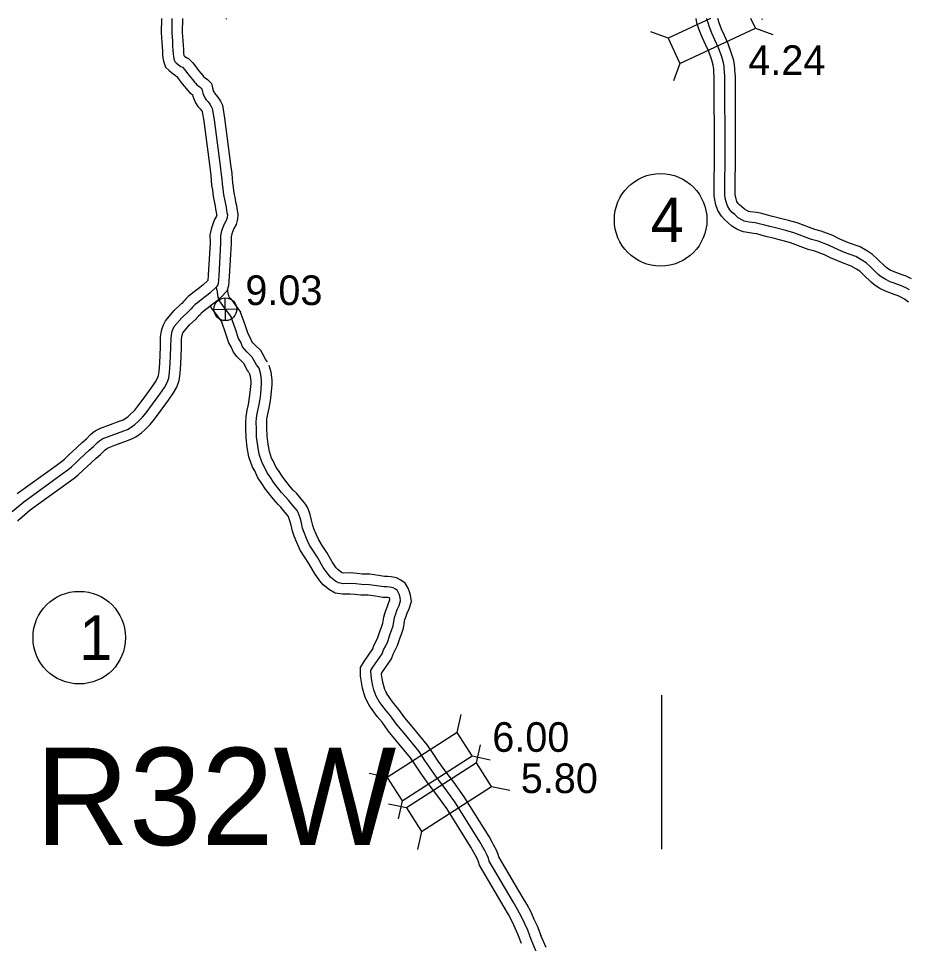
# Model space of a CAD drawing. Extents: x 31699 to 244310, y -8841 to 11474.
# Drawn here: x 100628 to 101474, y 4763 to 5642 of the extents above; entities that cross this region are included whole.
import ezdxf

# ---------------------------------------------------------------- set-up
doc = ezdxf.new("R2010")
doc.units = 0
for name, color, linetype in [('B_Logo', 7, 'Continuous'), ('Default', 7, 'Continuous'), ('Level 21', 7, 'Continuous'), ('R_Border', 7, 'Continuous'), ('R_Border Notes', 7, 'Continuous'), ('R_XS_EARTHWORK_STAGE1', 7, 'Continuous'), ('R_XS_EARTHWORK_STAGE2', 7, 'Continuous'), ('S_WALL', 7, 'Continuous'), ('S_WALL_ANNOT', 7, 'Continuous')]:
    doc.layers.add(name, color=color, linetype=linetype)

msp = doc.modelspace()

# ---------------------------------------------------------------- linework, layer by layer
at = {"layer": 'B_Logo'}
for points in [[(100773.57, 5642.27), (100773.39, 5628.8), (100773.94, 5620.58), (100774.24, 5615.9), (100774.55, 5612.15), (100774.66, 5608.54), (100774.91, 5606.07), (100775.23, 5604.06), (100775.56, 5603.06), (100776.08, 5601.72), (100777.67, 5600.24), (100779.53, 5598.55), (100782.05, 5596.6), (100783.51, 5595.92), (100785.9, 5593.5), (100787.55, 5591.22), (100791.12, 5586.59), (100793.37, 5583.9), (100794.95, 5581.88), (100795.88, 5580.67), (100797.2, 5579.26), (100799.19, 5577.85), (100800.59, 5576.7), (100802.04, 5575.29), (100802.37, 5573.95), (100803.02, 5571.21), (100803.61, 5569.6), (100804.79, 5566.98), (100806.11, 5564.97), (100807.96, 5563.02), (100809.62, 5560.81), (100811, 5558.66), (100811.92, 5556.78), (100813.72, 5546.08), (100819.44, 5502.26), (100820.45, 5493.97), (100820.88, 5489.16), (100821.26, 5484.74), (100821.9, 5480.73), (100822.27, 5477.12), (100822.91, 5473.17), (100823.43, 5470.49), (100824.33, 5465.94), (100824.98, 5462.86), (100825.36, 5459.92), (100825.81, 5457.98), (100826.27, 5455.64), (100826.05, 5453.3), (100825.23, 5450.43), (100823.28, 5446.97), (100820.83, 5440.43), (100819.74, 5435.69), (100819.83, 5428.88), (100818.02, 5397.81), (100817.57, 5390.19), (100816.9, 5388.39), (100815.48, 5386.8)], [(101283.24, 5638.27), (101282.46, 5640.68), (101282.16, 5642.27)], [(101474.81, 5384.33), (101471.87, 5386.06), (101467.88, 5388.02), (101463.56, 5389.52), (101459.37, 5391.08), (101456.31, 5392.1), (101451.52, 5394.41), (101448, 5396.7), (101445.09, 5399.12), (101437.67, 5406.32), (101433.62, 5409.96), (101429.57, 5412.65), (101423.66, 5416.1), (101413.15, 5419.91), (101403.85, 5423.91), (101397.87, 5426.75), (101387.82, 5430.63), (101381.64, 5432.27), (101364.94, 5438.59), (101357.29, 5440.77), (101347.37, 5443.24), (101342.05, 5444.48), (101337.19, 5445.78), (101332, 5447.21), (101328.07, 5447.97), (101322.21, 5448.74), (101319.41, 5449.23), (101317.75, 5449.78), (101315.29, 5450.86), (101311.97, 5452.95), (101308.66, 5455.85), (101306.27, 5458), (101304.02, 5460.42), (101301.71, 5464.11), (101300.34, 5468.06), (101299.56, 5471.48), (101299.18, 5474.82), (101299.14, 5478.16), (101299.51, 5514.79), (101299.24, 5586.64), (101298.75, 5592.65), (101298.69, 5594.53), (101298.44, 5597.07), (101298, 5600.21), (101296.23, 5605.84), (101293.16, 5614.48), (101289.87, 5621.85), (101286.85, 5628.35), (101284.29, 5634.85), (101283.24, 5638.27)], [(100815.48, 5386.8), (100809.98, 5381.62), (100806.37, 5378.7), (100804.22, 5377.04), (100801.94, 5375.32), (100799.73, 5373.66), (100797.79, 5372.07), (100795.71, 5370.48), (100794.17, 5368.95), (100793.23, 5367.89), (100791.75, 5366.36), (100789.94, 5364.5), (100789.27, 5363.83), (100782.91, 5357.88)], [(100815.48, 5386.8), (100815.87, 5385.06), (100816.14, 5384.45), (100816.33, 5383.72), (100816.46, 5382.51), (100816.58, 5381.58), (100816.77, 5380.04), (100817.29, 5377.63), (100817.81, 5375.62), (100818.54, 5374.08), (100819.92, 5371.6), (100821.77, 5369.51), (100829.74, 5358.57)], [(100621.68, 5173.63), (100632.6, 5183.09), (100669.18, 5209.44), (100674.59, 5213.33), (100677.95, 5216.12), (100682.74, 5220.61), (100685.83, 5223.46), (100694.9, 5232.02), (100698.91, 5235.42), (100702.92, 5239.29), (100704.89, 5241.19), (100705.81, 5241.87), (100707.93, 5242.98), (100710.84, 5244.22), (100715.94, 5246.1), (100727.74, 5250.49), (100731.18, 5251.81), (100733.96, 5253.26), (100738.31, 5256.33), (100741.14, 5258.91), (100743.96, 5261.69), (100745.67, 5263.32), (100749.2, 5267.66), (100755.21, 5275.9), (100762, 5285.23), (100766.5, 5291.71), (100768.97, 5296.23), (100770.63, 5300.6), (100771.29, 5305.83), (100771.9, 5314.26), (100772.54, 5329.78), (100772.8, 5338.88), (100773.53, 5343.43), (100773.91, 5344.98), (100774.67, 5347.33), (100775.78, 5349.42), (100782.91, 5357.88)], [(100856.37, 5309.96), (100853.99, 5313.2), (100849.95, 5320.56), (100845.16, 5325.11), (100842.92, 5327.55), (100840.75, 5330.32), (100838.95, 5334.64), (100836.77, 5338.29), (100833.98, 5346.87), (100829.74, 5358.57)], [(101115.24, 4766.95), (101111.77, 4775.92), (101108.95, 4782.03), (101106.06, 4788.54), (101102.22, 4795.64), (101097.99, 4802.73), (101075.23, 4841.57), (101074.39, 4844.3), (101073, 4847.62), (101070.61, 4852.2), (101069.24, 4854.59), (101066.43, 4859.7), (101043.23, 4896.93), (101033.43, 4910.55), (101025.15, 4921.26), (101018.55, 4930.66), (101014.12, 4937.21), (101008.46, 4945.62), (100994.22, 4962.93), (100987.03, 4971.58), (100981.25, 4979.52), (100976.63, 4985.2), (100973.51, 4989.3), (100970.65, 4993.33), (100969.42, 4995.39), (100969.01, 4996.05), (100967.84, 4998.31), (100966.67, 5000.9), (100965.63, 5004.16), (100964.63, 5008.15), (100963.56, 5013.29), (100962.89, 5017.96), (100962.82, 5022.77), (100964.7, 5025.94), (100973.31, 5038.44), (100974.79, 5042.2), (100976.8, 5046.24), (100978.74, 5050.22), (100981.1, 5057.34), (100982.31, 5060.57), (100983.85, 5065.14), (100984.76, 5071.17), (100985.51, 5073.99), (100986.34, 5076.47), (100987.49, 5079.63), (100988.26, 5081.85), (100989.49, 5084.27), (100991.02, 5088.98), (100990.57, 5092.11), (100989.73, 5095.04), (100989.11, 5096.5), (100987.74, 5098.89), (100986.13, 5100.07), (100983.91, 5101.17), (100980.64, 5101.79), (100977.9, 5102.02), (100974.9, 5102.11), (100968.49, 5103.09), (100960.95, 5104.11), (100953.75, 5104.27), (100948.55, 5104.93), (100943.21, 5105.32), (100936.35, 5105.08), (100932.01, 5105.82), (100928.99, 5107.51), (100924.4, 5111.32), (100921.96, 5114.16), (100917.47, 5120.45), (100912.21, 5129.6), (100908.11, 5136.16), (100904.36, 5141.85), (100901.47, 5148.23), (100899.19, 5153.81), (100897.8, 5157.87), (100896.65, 5163.13), (100895.32, 5167.86), (100893.64, 5172.92), (100892.48, 5174.77), (100888.62, 5179.33), (100884.54, 5184.48), (100881.71, 5187.25), (100877.71, 5191.73), (100870.71, 5200.66), (100866.62, 5207.01), (100864.04, 5210.65), (100861.08, 5217.03), (100859.23, 5220.08), (100856.52, 5228.19), (100855.07, 5236.13), (100854.01, 5244.6), (100853.82, 5252.56), (100853.67, 5258.24), (100853.94, 5262.72), (100854.99, 5268.15), (100856.04, 5273.72), (100857.34, 5280.49), (100857.93, 5285.71), (100858.86, 5294.95), (100858.81, 5298.23), (100857.99, 5304.03), (100856.37, 5309.96)], [(101120, 4755.72), (101115.24, 4766.95)]]:
    msp.add_lwpolyline(points, dxfattribs=at)
at = {"layer": 'Default'}
msp.add_line((101239.15, 4999.1), (101239.15, 4852.8), dxfattribs=at)
at = {"layer": 'Level 21'}
for p, q in [((100824.64, 5355.15), (100824.14, 5376.85)), ((100813.54, 5365.75), (100835.24, 5366.25))]:
    msp.add_line(p, q, dxfattribs=at)
msp.add_circle((100824.39, 5366), 10.85, dxfattribs=at)
at = {"layer": 'R_Border Notes'}
for centre in [(101238.18, 5450.95), (100685.48, 5053.87)]:
    msp.add_circle(centre, 44, dxfattribs=at)
at = {"layer": 'R_XS_EARTHWORK_STAGE1'}
for p, q in [((100824.76, 5642.27), (100825.4, 5641.59)), ((101334.42, 5642.27), (101334.73, 5641.25)), ((101245.41, 5623.54), (101228.88, 5629.58)), ((101328.35, 5633.01), (101344.89, 5626.97)), ((101256.54, 5599.61), (101250.51, 5583.07)), ((101044.78, 4963.74), (101048.54, 4980.93)), ((101063.22, 4934.74), (101066.98, 4951.94)), ((101059.03, 4941.52), (101076.23, 4937.76)), ((100978.11, 4920.99), (100960.92, 4924.75)), ((101077.47, 4912.52), (101094.67, 4908.76)), ((100992.36, 4898.77), (100988.6, 4881.57)), ((100996.55, 4891.99), (100979.36, 4895.75)), ((101010.8, 4869.77), (101007.04, 4852.58))]:
    msp.add_line(p, q, dxfattribs=at)
msp.add_lwpolyline([(101285.66, 5642.27), (101245.41, 5623.54), (101256.54, 5599.61), (101328.35, 5633.01), (101324.05, 5642.27)], dxfattribs=at)
for points in [[(100992.36, 4898.77), (101059.03, 4941.52), (101044.78, 4963.74), (100978.11, 4920.99)], [(101010.8, 4869.77), (101077.47, 4912.52), (101063.22, 4934.74), (100996.55, 4891.99)]]:
    msp.add_lwpolyline(points, close=True, dxfattribs=at)
at = {"layer": 'R_XS_EARTHWORK_STAGE2'}
for points in [[(100763.56, 5642.27), (100763.39, 5628.53), (100763.96, 5619.92), (100764.27, 5615.16), (100764.56, 5611.59), (100764.68, 5607.89), (100764.99, 5604.78), (100765.48, 5601.71), (100766.14, 5599.68), (100767.6, 5595.95), (100770.91, 5592.87), (100773.1, 5590.89), (100776.82, 5588), (100777.66, 5587.61), (100778.24, 5587.03), (100779.53, 5585.24), (100783.32, 5580.32), (100785.6, 5577.59), (100787.06, 5575.75), (100788.24, 5574.2), (100790.59, 5571.69), (100793.04, 5569.95), (100793.42, 5568.32), (100794.35, 5565.81), (100796, 5562.15), (100798.24, 5558.73), (100800.31, 5556.56), (100801.4, 5555.1), (100802.28, 5553.73), (100802.3, 5553.69), (100803.83, 5544.6), (100809.51, 5501.01), (100810.5, 5492.91), (100810.92, 5488.29), (100811.32, 5483.53), (100811.98, 5479.42), (100812.36, 5475.8), (100813.07, 5471.42), (100813.62, 5468.57), (100814.54, 5463.94), (100815.11, 5461.19), (100815.51, 5458.14), (100816.03, 5455.89), (100816.18, 5455.14), (100815.94, 5454.32), (100814.18, 5451.2), (100811.24, 5443.32), (100809.72, 5436.77), (100809.82, 5429.1), (100808.04, 5398.39), (100807.74, 5393.35)], [(100783.57, 5642.27), (100783.4, 5629.07), (100783.92, 5621.23), (100784.22, 5616.63), (100784.54, 5612.72), (100784.65, 5609.2), (100784.83, 5607.36), (100784.85, 5607.23), (100785.96, 5606.22), (100787.28, 5605.2), (100789.36, 5604.23), (100793.55, 5599.98), (100795.56, 5597.2), (100798.92, 5592.85), (100801.13, 5590.2), (100802.85, 5588.02), (100803.52, 5587.15), (100803.81, 5586.83), (100805.28, 5585.79), (100807.25, 5584.17), (100811.08, 5580.46), (100812.09, 5576.28), (100812.61, 5574.09), (100812.87, 5573.39), (100813.58, 5571.82), (100813.98, 5571.21), (100815.62, 5569.48), (100817.84, 5566.51), (100819.72, 5563.59), (100821.54, 5559.88), (100823.61, 5547.55), (100829.36, 5503.52), (100830.39, 5495.03), (100830.85, 5490.02), (100831.19, 5485.95), (100831.81, 5482.04), (100832.19, 5478.44), (100832.76, 5474.92), (100833.24, 5472.41), (100834.13, 5467.94), (100834.85, 5464.54), (100835.21, 5461.71), (100835.6, 5460.07), (100836.35, 5456.14), (100835.92, 5451.45), (100834.52, 5446.55), (100832.37, 5442.73), (100830.43, 5437.54), (100829.75, 5434.62), (100829.83, 5428.65), (100828.01, 5397.22), (100827.47, 5388.09), (100825.6, 5383.15), (100822.98, 5380.17)], [(101274.84, 5631.55), (101273.71, 5635.26), (101272.75, 5638.2), (101271.99, 5642.27)], [(101296.04, 5632.29), (101293.74, 5638.15), (101292.78, 5641.27), (101292.46, 5642.27)], [(101473.85, 5372.55), (101470.01, 5375.55), (101467.11, 5377.25), (101464.02, 5378.78), (101460.17, 5380.11), (101456.03, 5381.65), (101452.54, 5382.82), (101446.6, 5385.68), (101442.06, 5388.64), (101438.4, 5391.68), (101430.84, 5399.01), (101427.48, 5402.04), (101424.28, 5404.17), (101419.41, 5407.01), (101409.47, 5410.61), (101399.72, 5414.8), (101393.91, 5417.56), (101384.73, 5421.1), (101378.57, 5422.73), (101361.79, 5429.09), (101354.71, 5431.11), (101345.04, 5433.52), (101339.63, 5434.77), (101334.57, 5436.13), (101329.71, 5437.47), (101326.47, 5438.1), (101320.7, 5438.86), (101316.99, 5439.5), (101314.17, 5440.43), (101310.58, 5442.01), (101305.98, 5444.91), (101302.02, 5448.37), (101299.25, 5450.87), (101296.05, 5454.31), (101292.64, 5459.76), (101290.71, 5465.3), (101289.68, 5469.8), (101289.19, 5474.19), (101289.14, 5478.15), (101289.51, 5514.82), (101289.24, 5586.21), (101288.76, 5592.1), (101288.71, 5593.89), (101288.51, 5595.87), (101288.21, 5598), (101286.75, 5602.66), (101283.86, 5610.76), (101280.77, 5617.71), (101277.65, 5624.41), (101274.84, 5631.55)], [(101476.62, 5394.87), (101471.74, 5397.27), (101466.94, 5398.93), (101462.7, 5400.51), (101460.07, 5401.39), (101456.44, 5403.14), (101453.95, 5404.76), (101451.77, 5406.57), (101444.49, 5413.63), (101439.77, 5417.88), (101434.87, 5421.14), (101427.92, 5425.19), (101416.84, 5429.21), (101407.97, 5433.02), (101401.82, 5435.95), (101390.92, 5440.15), (101384.7, 5441.8), (101368.09, 5448.09), (101359.87, 5450.44), (101349.71, 5452.96), (101344.47, 5454.18), (101339.82, 5455.43), (101334.29, 5456.96), (101329.68, 5457.85), (101323.72, 5458.63), (101321.84, 5458.96), (101321.33, 5459.12), (101320, 5459.71), (101317.96, 5461), (101315.3, 5463.33), (101313.3, 5465.13), (101311.99, 5466.53), (101310.79, 5468.46), (101309.96, 5470.82), (101309.43, 5473.15), (101309.17, 5475.45), (101309.14, 5478.18), (101309.51, 5514.75), (101309.24, 5587.06), (101308.73, 5593.21), (101308.68, 5595.16), (101308.37, 5598.26), (101307.78, 5602.42), (101305.72, 5609.01), (101302.45, 5618.2), (101298.97, 5625.99), (101296.04, 5632.29)], [(100807.82, 5393.31), (100803.41, 5389.16), (100800.17, 5386.55), (100798.15, 5384.99), (100795.93, 5383.31), (100793.56, 5381.53), (100791.58, 5379.91), (100789.13, 5378.03), (100786.9, 5375.82), (100785.88, 5374.68), (100784.58, 5373.32), (100782.84, 5371.54), (100782.33, 5371.04), (100775.66, 5364.79)], [(100822.91, 5380.05), (100816.56, 5374.07), (100812.56, 5370.85), (100810.3, 5369.1), (100807.96, 5367.33), (100805.9, 5365.79), (100804, 5364.23), (100802.3, 5362.93), (100801.44, 5362.08), (100800.57, 5361.1), (100798.93, 5359.4), (100797.04, 5357.46), (100796.21, 5356.63), (100790.19, 5350.99)], [(100826.28, 5384.75), (100826.39, 5383.71), (100826.5, 5382.86), (100826.64, 5381.71), (100827.02, 5379.93), (100827.26, 5379.03), (100827.44, 5378.64), (100828.12, 5377.43), (100829.57, 5375.8), (100838.69, 5363.26)], [(100626.39, 5190.94), (100663.34, 5217.55), (100668.46, 5221.24), (100671.33, 5223.63), (100675.94, 5227.93), (100679.01, 5230.77), (100688.23, 5239.47), (100692.2, 5242.84), (100695.97, 5246.49), (100698.42, 5248.84), (100700.5, 5250.38), (100703.65, 5252.02), (100707.14, 5253.52), (100712.47, 5255.48), (100724.2, 5259.84), (100727.07, 5260.94), (100728.74, 5261.81), (100732.03, 5264.14), (100734.25, 5266.17), (100737, 5268.87), (100738.32, 5270.13), (100741.28, 5273.77), (100747.13, 5281.79), (100753.85, 5291.02), (100757.98, 5296.98), (100759.87, 5300.43), (100760.86, 5303.04), (100761.34, 5306.81), (100761.91, 5314.82), (100762.54, 5330.13), (100762.82, 5339.82), (100763.72, 5345.42), (100764.28, 5347.71), (100765.43, 5351.24), (100767.43, 5355.04), (100775.59, 5364.7)], [(100810.05, 5368.77), (100811.72, 5365.77), (100813.98, 5363.23), (100820.88, 5353.75)], [(100864.43, 5315.88), (100862.44, 5318.59), (100857.97, 5326.75), (100852.29, 5332.12), (100850.56, 5334.01), (100849.46, 5335.42), (100847.91, 5339.16), (100845.93, 5342.46), (100843.43, 5350.12), (100838.72, 5363.13)], [(100847.1, 5305.69), (100845.54, 5307.81), (100841.94, 5314.38), (100838.02, 5318.09), (100835.29, 5321.08), (100832.04, 5325.23), (100830, 5330.13), (100827.61, 5334.12), (100824.52, 5343.62), (100820.85, 5353.76)], [(100627.01, 5164.42), (100627.95, 5165.73), (100628.56, 5166.36), (100638.81, 5175.24), (100675.03, 5201.32), (100680.72, 5205.42), (100684.56, 5208.62), (100689.55, 5213.28), (100692.66, 5216.15), (100701.57, 5224.56), (100705.63, 5228), (100709.87, 5232.1), (100711.25, 5233.43), (100712.21, 5233.93), (100714.54, 5234.93), (100719.42, 5236.72), (100731.27, 5241.13), (100735.3, 5242.68), (100739.18, 5244.7), (100744.59, 5248.52), (100748.02, 5251.66), (100750.92, 5254.52), (100753.02, 5256.52), (100757.12, 5261.55), (100763.29, 5270.01), (100770.15, 5279.43), (100775.02, 5286.45), (100778.07, 5292.03), (100780.41, 5298.16), (100781.25, 5304.84), (100781.88, 5313.69), (100782.53, 5329.43), (100782.78, 5337.93), (100783.34, 5341.45), (100783.54, 5342.24), (100783.92, 5343.42), (100784.12, 5343.8), (100790.18, 5350.99)], [(101124.57, 4770.55), (101120.99, 4779.82), (101118.06, 4786.16), (101115.04, 4792.96), (101110.92, 4800.58), (101106.59, 4807.82), (101084.44, 4845.63), (101083.8, 4847.7), (101082.07, 4851.87), (101079.38, 4857.01), (101077.96, 4859.48), (101075.06, 4864.75), (101051.54, 4902.5), (101041.45, 4916.53), (101033.2, 4927.2), (101026.78, 4936.33), (101022.41, 4942.8), (101016.49, 4951.6), (101001.92, 4969.3), (100994.92, 4977.72), (100989.18, 4985.62), (100984.49, 4991.38), (100981.57, 4995.22), (100979.03, 4998.8), (100977.96, 5000.58), (100977.72, 5000.98), (100976.85, 5002.66), (100976.02, 5004.5), (100975.25, 5006.89), (100974.38, 5010.38), (100973.41, 5015.02), (100972.88, 5018.74), (100972.86, 5020.09), (100973.13, 5020.54), (100982.2, 5033.71), (100983.94, 5038.15), (100985.77, 5041.83), (100988.02, 5046.43), (100990.52, 5054), (100991.74, 5057.21), (100993.6, 5062.78), (100994.56, 5069.12), (100995.09, 5071.1), (100995.78, 5073.18), (100996.92, 5076.28), (100997.49, 5077.94), (100998.76, 5080.44), (101001.25, 5088.09), (101000.38, 5094.21), (100999.17, 5098.39), (100998.08, 5100.96), (100995.36, 5105.71), (100991.34, 5108.64), (100987.13, 5110.74), (100981.99, 5111.72), (100978.47, 5112.01), (100975.81, 5112.09), (100969.92, 5112.98), (100961.74, 5114.1), (100954.49, 5114.26), (100949.54, 5114.88), (100943.4, 5115.33), (100937.03, 5115.11), (100935.39, 5115.39), (100934.67, 5115.79), (100931.44, 5118.48), (100929.84, 5120.34), (100925.89, 5125.86), (100920.78, 5134.74), (100916.53, 5141.55), (100913.15, 5146.69), (100910.66, 5152.18), (100908.55, 5157.33), (100907.44, 5160.56), (100906.36, 5165.55), (100904.88, 5170.79), (100902.76, 5177.2), (100900.58, 5180.69), (100896.36, 5185.66), (100891.99, 5191.19), (100888.94, 5194.16), (100885.38, 5198.15), (100878.87, 5206.46), (100874.91, 5212.62), (100872.72, 5215.7), (100869.92, 5221.74), (100868.36, 5224.3), (100866.23, 5230.69), (100864.95, 5237.65), (100863.99, 5245.34), (100863.82, 5252.81), (100863.68, 5258.07), (100863.88, 5261.47), (100864.81, 5266.27), (100865.87, 5271.85), (100867.24, 5278.99), (100867.87, 5284.65), (100868.87, 5294.53), (100868.8, 5299), (100867.81, 5306.06), (100866.02, 5312.6)], [(101105.91, 4763.35), (101102.56, 4772.02), (101099.84, 4777.9), (101097.08, 4784.13), (101093.53, 4790.7), (101089.38, 4797.64), (101066.01, 4837.52), (101064.97, 4840.9), (101063.94, 4843.37), (101061.84, 4847.39), (101060.52, 4849.69), (101057.8, 4854.64), (101034.92, 4891.36), (101025.42, 4904.57), (101017.1, 4915.33), (101010.31, 4924.99), (101005.83, 4931.62), (101000.44, 4939.64), (100986.51, 4956.55), (100979.13, 4965.43), (100973.32, 4973.42), (100968.77, 4979.01), (100965.45, 4983.37), (100962.27, 4987.87), (100960.88, 4990.19), (100960.3, 4991.12), (100958.84, 4993.95), (100957.33, 4997.3), (100956, 5001.42), (100954.88, 5005.92), (100953.71, 5011.55), (100952.9, 5017.17), (100952.78, 5025.45), (100956.28, 5031.34), (100964.42, 5043.16), (100965.64, 5046.26), (100967.82, 5050.66), (100969.45, 5054), (100971.67, 5060.68), (100972.89, 5063.92), (100974.09, 5067.49), (100974.95, 5073.22), (100975.93, 5076.87), (100976.9, 5079.77), (100978.07, 5082.98), (100979.03, 5085.76), (100980.22, 5088.11), (100980.79, 5089.86), (100980.77, 5090.02), (100980.29, 5091.68), (100979.29, 5091.87), (100977.34, 5092.03), (100974, 5092.13), (100967.07, 5093.19), (100960.16, 5094.13), (100953.01, 5094.29), (100947.55, 5094.98), (100943.02, 5095.31), (100935.68, 5095.05), (100928.63, 5096.25), (100923.3, 5099.24), (100917.37, 5104.17), (100914.08, 5107.99), (100909.05, 5115.04), (100903.63, 5124.45), (100899.69, 5130.76), (100895.58, 5137.01), (100892.28, 5144.27), (100889.82, 5150.29), (100888.15, 5155.17), (100886.95, 5160.71), (100885.75, 5164.93), (100884.53, 5168.63), (100884.39, 5168.85), (100880.88, 5172.99), (100877.1, 5177.77), (100874.47, 5180.33), (100870.03, 5185.32), (100862.56, 5194.85), (100858.34, 5201.41), (100855.35, 5205.61), (100852.24, 5212.32), (100850.1, 5215.85), (100846.81, 5225.69), (100845.18, 5234.61), (100844.02, 5243.87), (100843.83, 5252.31), (100843.67, 5258.4), (100844, 5263.98), (100845.17, 5270.03), (100846.22, 5275.59), (100847.45, 5281.99), (100847.99, 5286.77), (100848.85, 5295.38), (100848.82, 5297.45), (100848.18, 5302.01), (100847.27, 5305.34)], [(101129.26, 4759.49), (101124.44, 4770.85)]]:
    msp.add_lwpolyline(points, dxfattribs=at)

# ---------------------------------------------------------------- texts
at = {"layer": 'R_Border'}
msp.add_text('R32W', height=92.4, dxfattribs=at).set_placement((100643.54, 4856.8))
at = {"layer": 'R_Border Notes'}
for s, p in [('4', (101228.73, 5429.83)), ('1', (100685.48, 5032.75))]:
    msp.add_text(s, height=42.24, dxfattribs=at).set_placement(p)
at = {"layer": 'S_WALL'}
for s, p in [('4.24', (101321.52, 5588.58)), ('6.00', (101078.14, 4945.35)), ('5.80', (101105.21, 4906.19))]:
    msp.add_text(s, height=28.16, dxfattribs=at).set_placement(p)
at = {"layer": 'S_WALL_ANNOT'}
msp.add_text('9.03', height=28.16, dxfattribs=at).set_placement((100843.37, 5369.96))

doc.saveas('drawing.dxf')
